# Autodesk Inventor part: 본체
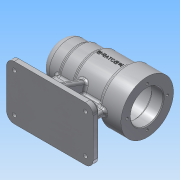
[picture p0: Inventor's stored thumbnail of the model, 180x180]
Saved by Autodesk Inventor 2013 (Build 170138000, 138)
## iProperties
Created: 2016-06
Part Number: 본체
Material: 알루미늄 6061
Document SubType Name: Modeling
Designer: mrc
Density: 2.71 g/cm^3
Mass: 673.897 g
Surface Area: 647.222 cm^2
Volume: 248.67 cm^3
Author: mrc
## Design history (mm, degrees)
sketch "스케치1"
  geometry: L1 (-56, 0)-(-56, 25); L2 (-56, 25)-(-31, 25); L3 (-31, 25)-(-31, 27); L4 (-31, 27)-(-11, 27); L5 (-11, 27)-(-11, 30); L6 (-11, 30)-(28, 30); L7 (28, 30)-(28, 34); L8 (28, 34)-(56, 34); L9 (56, 34)-(56, 0); L10 (-56, 0)-(56, 0); 3 further points
  constraints: 20 end point, 6 parallel, 2 coincident, 1 midpoint, 1 perpendicular, 1 vertical
  dimensions: "d5" = 112 distance between parallel lines of L9 L1; "d6" = 84 distance between parallel lines of L7 L1; "d7" = 45 distance between parallel lines of L1 L5; "d8" = 25 distance between parallel lines of L1 L3; "d9" = 68 diameter of L8 L10; "d10" = 60 diameter of L6 L10; "d11" = 54 diameter of L4 L10; "d12" = 50 diameter of L2 L10
revolve "회전1" sketch "스케치1" stored, may be unused: angle "d13" = 90 deg
hole "구멍1" diameter "d16" = 42; stored, may be unused: countersink angle "d20" = 90 deg, drill point angle "d22" = 0 deg; dims "d14" = 10, "d15" = 10, "d17" = 6, "d18" = 4, "d19" = 2, "d21" = 15
hole "구멍2" diameter "d25" = 48; stored, may be unused: countersink angle "d29" = 90 deg, drill point angle "d31" = 0 deg; dims "d23" = 10, "d24" = 10, "d26" = 6, "d27" = 4, "d28" = 2, "d30" = 54
sketch "스케치2"
  geometry: C1 r 24 at (0, 0) reference; C2 r 21 at (0, 0)
  constraints: 1 centre point, 1 coincident
  dimensions: "d32" = 42 diameter of C2
extrude "돌출1" cut sketch "스케치2" distance "d33" = 12; taper "d34" = 0 deg
sketch "스케치3"
  geometry: C1 r 21 at (0, 0) reference; C2 r 17.5 at (0, 0)
  constraints: 1 centre point, 1 coincident
  dimensions: "d35" = 35 diameter of C2
extrude "돌출2" cut sketch "스케치3" distance "d36" = 18; taper "d37" = 0 deg
sketch "스케치4"
  geometry: C1 r 17.5 at (0, 0) reference; C2 r 16 at (0, 0)
  constraints: 1 centre point, 1 coincident
  dimensions: "d38" = 32 diameter of C2
extrude "돌출3" cut sketch "스케치4" distance "d39" = 4; taper "d40" = 0 deg
sketch "스케치5"
  geometry: C1 r 16 at (0, 0) reference; C2 r 10.5 at (0, 0)
  constraints: 1 centre point, 1 coincident
  dimensions: "d41" = 21 diameter of C2
extrude "돌출4" cut sketch "스케치5" distance "d42" = 3; taper "d43" = 0 deg
fillet "모깎기1" dims "d44" = 10
fillet "모깎기2" dims "d45" = 3
chamfer "모따기1" distance "d46" = 1; stored, may be unused: second distance "d47" = 2, angle "d48" = 45 deg
fillet "모깎기3" dims "d49" = 3
fillet "모깎기4" dims "d50" = 3
fillet "모깎기5" dims "d51" = 3
fillet "모깎기6" dims "d52" = 0.3
node "작업 평면1"
sketch "스케치6"
  geometry: L1 (56, -35)-(-56, -35); L2 (-56, -35)-(-56, 35); L3 (-56, 35)-(56, 35); L4 (56, 35)-(56, -35); L5 (56, -35)-(-56, 35); L6 (-56, -35)-(56, 35); 1 further point
  constraints: 12 end point, 2 midpoint, 2 parallel, 1 horizontal, 1 perpendicular
  dimensions: "d54" = 112 distance of L2.end L3.end; "d55" = 70 distance of L1.end L2.end
extrude "돌출5" join sketch "스케치6" distance "d56" = 10; taper "d57" = 0 deg
sketch "스케치7"
  geometry: L1 (-4, 4)-(4, 4); L2 (4, 4)-(4, -4); L3 (4, -4)-(-4, -4); L4 (-4, -4)-(-4, 4); L5 (-4, 4)-(4, -4); L6 (4, 4)-(-4, -4); 1 further point
  constraints: 12 end point, 2 midpoint, 2 parallel, 1 horizontal, 1 perpendicular
  dimensions: "d58" = 8 distance of L2.end L3.end; "d59" = 8 distance of L1.end L2.end
extrude "돌출6" join sketch "스케치7" stored distance "d60" = 10; taper "d61" = 0 deg
sketch "스케치8"
  geometry: L1 (25, -30)-(4, -30) reference; L2 (4, -30)-(4, -60) reference; L3 (4, -60)-(56, -60) reference; L4 (56, -60)-(56, -70) reference; L5 (56, -70)-(-56, -70) reference; L6 (-56, -70)-(-56, -60) reference; L7 (-56, -60)-(-4, -60) reference; L8 (-4, -60)-(-4, -30) reference; L9 (-4, -30)-(-8.804, -30) reference; L10 (-14, -27)-(-29.356, -27) reference; L11 (-33.828, -25)-(-46, -25) reference; L12 (-56, -15)-(-56, 15) reference; L13 (-46, 25)-(-33.828, 25) reference; L14 (-29.356, 27)-(-14, 27) reference; L15 (-8.804, 30)-(25, 30) reference; L16 (30.657, 34)-(56, 34) reference; L17 (56, 34)-(56, 22) reference; L18 (56, 22)-(55, 21) reference; L19 (55, 21)-(41, 21) reference; L20 (38, 24)-(-10, 24) reference; L21 (-13, 21)-(-24.7, 21) reference; L22 (-25, 20.7)-(-25, 17.5) reference; L23 (-25, 17.5)-(-42.7, 17.5) reference; L24 (-43, 17.2)-(-43, 16) reference; L25 (-43, 16)-(-46.7, 16) reference; L26 (-47, 15.7)-(-47, 10.5) reference; L27 (-50, 7.5)-(-50, -7.5) reference; L28 (-47, -10.5)-(-47, -15.7) reference; L29 (-46.7, -16)-(-43, -16) reference; L30 (-43, -16)-(-43, -17.2) reference; L31 (-42.7, -17.5)-(-25, -17.5) reference; L32 (-25, -17.5)-(-25, -20.7) reference; L33 (-24.7, -21)-(-13, -21) reference; L34 (-10, -24)-(38, -24) reference; L35 (41, -21)-(55, -21) reference; L36 (55, -21)-(56, -22) reference; L37 (56, -22)-(56, -34) reference; L38 (56, -34)-(30.657, -34) reference; L39 (-36, -25)-(-36, -60); L40 (36, -60)-(36, -34); A1 r 3 centre (30.657, -31) between (27.828, -32) and (30.657, -34) reference; A2 r 3 centre (25, -33) between (27.828, -32) and (25, -30) reference; A3 r 3 centre (-8.804, -27) between (-11.402, -28.5) and (-8.804, -30) reference; A4 r 3 centre (-14, -30) between (-11.402, -28.5) and (-14, -27) reference; A5 r 3 centre (-29.356, -24) between (-31.592, -26) and (-29.356, -27) reference; A6 r 3 centre (-33.828, -28) between (-31.592, -26) and (-33.828, -25) reference; A7 r 10 centre (-46, -15) between (-56, -15) and (-46, -25) reference; A8 r 10 centre (-46, 15) between (-46, 25) and (-56, 15) reference; A9 r 3 centre (-33.828, 28) between (-33.828, 25) and (-31.592, 26) reference; A10 r 3 centre (-29.356, 24) between (-29.356, 27) and (-31.592, 26) reference; A11 r 3 centre (-14, 30) between (-14, 27) and (-11.402, 28.5) reference; A12 r 3 centre (-8.804, 27) between (-8.804, 30) and (-11.402, 28.5) reference; A13 r 3 centre (25, 33) between (25, 30) and (27.828, 32) reference; A14 r 3 centre (30.657, 31) between (30.657, 34) and (27.828, 32) reference; A15 r 3 centre (38, 21) between (41, 21) and (38, 24) reference; A16 r 3 centre (-10, 21) between (-10, 24) and (-13, 21) reference; A17 r 0.3 centre (-24.7, 20.7) between (-24.7, 21) and (-25, 20.7) reference; A18 r 0.3 centre (-42.7, 17.2) between (-42.7, 17.5) and (-43, 17.2) reference; A19 r 0.3 centre (-46.7, 15.7) between (-46.7, 16) and (-47, 15.7) reference; A20 r 3 centre (-47, 7.5) between (-47, 10.5) and (-50, 7.5) reference; A21 r 3 centre (-47, -7.5) between (-50, -7.5) and (-47, -10.5) reference; A22 r 0.3 centre (-46.7, -15.7) between (-47, -15.7) and (-46.7, -16) reference; A23 r 0.3 centre (-42.7, -17.2) between (-43, -17.2) and (-42.7, -17.5) reference; A24 r 0.3 centre (-24.7, -20.7) between (-25, -20.7) and (-24.7, -21) reference; A25 r 3 centre (-10, -21) between (-13, -21) and (-10, -24) reference; A26 r 3 centre (38, -21) between (38, -24) and (41, -21) reference; 1 further point
  constraints: 4 end point, 4 point on line, 2 perpendicular
  dimensions: "d62" = 20 distance between parallel lines of L39 L6; "d63" = 20 distance between parallel lines of L4 L40
  node "절단 모서리 투영1"
feature "리브1" dims "d64" = 1, "d65" = 8, "d66" = 0, "d67" = 0, "d68" = 1, "d69" = 1
feature "리브2" dims "d70" = 1, "d71" = 8, "d72" = 0, "d73" = 0, "d74" = 1, "d75" = 1
sketch "스케치9"
  geometry: L1 (-60, -4)-(-60, -35) reference; L2 (-60, -35)-(-70, -35) reference; L3 (-70, -35)-(-70, 35) reference; L4 (-70, 35)-(-60, 35) reference; L5 (-60, 35)-(-60, 4) reference; L6 (-60, 4)-(-29.732, 4) reference; L7 (-29.732, -4)-(-60, -4) reference; L8 (-60, 28)-(-25.68, 15.509); L9 (-25.68, -15.509)-(-60, -28); C1 r 24 at (0, 0) reference; A1 r 30 centre (0, 0) between (-29.732, -4) and (-29.732, 4) reference; 1 further point
  constraints: 4 end point, 2 point on circle, 2 point on line
  dimensions: "d76" = 110 deg angle of L5 L8; "d77" = 110 deg angle of L1 L9; "d78" = 7 distance from line of L8.start L4; "d79" = 7 distance from line of L2 L9.end
  node "절단 모서리 투영2"
feature "리브3" dims "d80" = 1, "d81" = 8, "d82" = 0, "d83" = 0, "d84" = 1, "d85" = 1
feature "리브4" dims "d86" = 1, "d87" = 8, "d88" = 0, "d89" = 0, "d90" = 1, "d91" = 1
fillet "모깎기7" dims "d92" = 10
chamfer "모따기2" distance "d93" = 4; stored, may be unused: second distance "d94" = 2, angle "d95" = 45 deg
sketch "스케치11"
  geometry: A1 r 6 centre (-46, -25) between (-52, -25) and (-46, -31) reference; 1 further point
hole "구멍3" sketch "스케치11" at (-46, -25) diameter "d96" = 5; stored, may be unused: countersink angle "d100" = 90 deg, drill point angle "d102" = 0 deg; dims "d97" = 6, "d98" = 9, "d99" = 4, "d101" = 54
node "작업 평면2"
sketch "스케치12"
  geometry: L1 (54.66, -64)-(54.66, -70) reference; L2 (54.66, -70)-(-54.66, -70) reference; L3 (-54.66, -70)-(-54.66, -64) reference; L4 (-49.317, -60)-(49.317, -60) reference; L5 (30.657, 16)-(56, 16) reference; L6 (56, 16)-(56, -16) reference; L7 (56, -16)-(30.657, -16) reference; L8 (-8.804, 0)-(25, 0) reference; L9 (56, -34)-(56, 34) reference; L10 (30.657, -33.764)-(30.657, -33.764) reference; L11 (30.657, -33.764)-(36, -33.764) reference; L12 (36, -33.764)-(36, -33.764) reference; L13 (36, -33.764)-(30.657, -33.764) reference; 4 further points
  constraints: 1 horizontal alignment, 7 other
  dimensions: "d110" = 48 distance from line of L6 point (8, 0)
feature "엠보싱1" sketch "스케치12" dims "d5" = 112, "d6" = 84, "d7" = 45, "d8" = 25, "d9" = 68, "d10" = 60, "d11" = 54, "d12" = 50, "d30" = 54, "d111" = 0.5, "d112" = 0
fillet "모깎기8" dims "d113" = 3
fillet "모깎기9" dims "d114" = 3
sketch "스케치13"
  geometry: C1 r 22 at (0, 0) reference; 1 further point
  constraints: 1 vertical alignment
  dimensions: "d115" = 26 distance of C1.centre point (0, 26)
hole "구멍4" sketch "스케치13" at (0, 26) diameter "d116" = 3.242; stored, may be unused: countersink angle "d120" = 90 deg, drill point angle "d122" = 118 deg; dims "d117" = 8, "d118" = 9, "d119" = 4, "d121" = 11
node "솔리드1"
pattern_linear "직사각형 패턴1" dims "d105" = 50, "d108" = 92
pattern_circular "원형 패턴1" dims angle "d124" = 360 deg
node "투영된 루프1"
node "절단 모서리 투영3"
